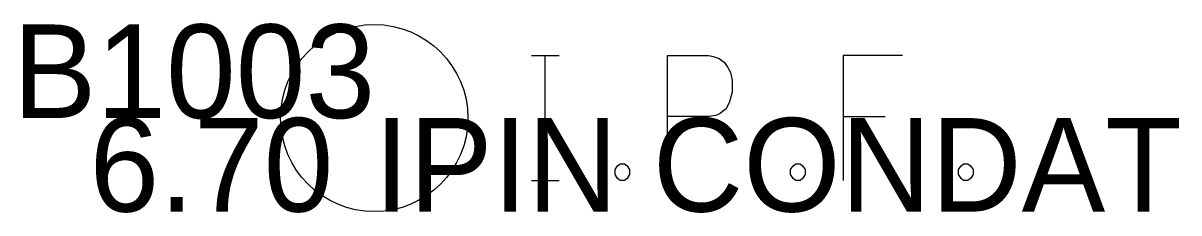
# Model space of a CAD drawing. Extents: x 2177554 to 2180444, y 721535 to 723442.
# Drawn here: x 2177888.173 to 2177888.913, y 721644.555 to 721644.677 of the extents above; entities that cross this region are included whole.
import ezdxf

# ---------------------------------------------------------------- set-up
doc = ezdxf.new("R2010")
doc.units = 0
for name, color, linetype in [('SV_X_Mon_Cells_Found', 7, 'Continuous'), ('SV_X_Text_Comment', 7, 'Continuous'), ('SV_X_Text_Elevation', 7, 'Continuous'), ('SV_X_Text_Name', 7, 'Continuous')]:
    doc.layers.add(name, color=color, linetype=linetype)

msp = doc.modelspace()

# ---------------------------------------------------------------- linework, layer by layer
at = {"layer": 'SV_X_Mon_Cells_Found'}
for points in [[(2177888.49872, 721644.656), (2177888.51636, 721644.656)], [(2177888.50754, 721644.576), (2177888.50754, 721644.656)], [(2177888.5858, 721644.576), (2177888.5858, 721644.656), (2177888.61226, 721644.656), (2177888.61502, 721644.65537), (2177888.61887, 721644.65411), (2177888.62053, 721644.65285), (2177888.62218, 721644.65159), (2177888.62438, 721644.64844), (2177888.62604, 721644.64529), (2177888.62714, 721644.64025), (2177888.62714, 721644.63269), (2177888.62659, 721644.63017), (2177888.62548, 721644.62639), (2177888.62328, 721644.62199), (2177888.62107, 721644.62009), (2177888.61942, 721644.61883), (2177888.61666, 721644.61757), (2177888.61226, 721644.61695), (2177888.5858, 721644.61695)], [(2177888.73627, 721644.656), (2177888.69823, 721644.656), (2177888.69823, 721644.576)], [(2177888.69823, 721644.61695), (2177888.72524, 721644.61695)], [(2177888.55549, 721644.58671), (2177888.55824, 721644.58671), (2177888.5599, 721644.58545), (2177888.56155, 721644.58293), (2177888.56155, 721644.57978), (2177888.5599, 721644.57726), (2177888.55824, 721644.576), (2177888.55549, 721644.576), (2177888.55383, 721644.57726), (2177888.55218, 721644.57978), (2177888.55218, 721644.58293), (2177888.55383, 721644.58545), (2177888.55549, 721644.58671)], [(2177888.66793, 721644.58671), (2177888.67068, 721644.58671), (2177888.67233, 721644.58545), (2177888.67398, 721644.58293), (2177888.67398, 721644.57978), (2177888.67233, 721644.57726), (2177888.67068, 721644.576), (2177888.66793, 721644.576), (2177888.66627, 721644.57726), (2177888.66462, 721644.57978), (2177888.66462, 721644.58293), (2177888.66627, 721644.58545), (2177888.66793, 721644.58671)], [(2177888.77539, 721644.58671), (2177888.77815, 721644.58671), (2177888.7798, 721644.58545), (2177888.78145, 721644.58293), (2177888.78145, 721644.57978), (2177888.7798, 721644.57726), (2177888.77815, 721644.576), (2177888.77539, 721644.576), (2177888.77374, 721644.57726), (2177888.77209, 721644.57978), (2177888.77209, 721644.58293), (2177888.77374, 721644.58545), (2177888.77539, 721644.58671)], [(2177888.49872, 721644.576), (2177888.51636, 721644.576)]]:
    msp.add_lwpolyline(points, dxfattribs=at)
msp.add_circle((2177888.398, 721644.616), 0.06, dxfattribs=at)

# ---------------------------------------------------------------- texts
at = {"layer": 'SV_X_Text_Comment'}
msp.add_text('IPIN CONDAT', height=0.06, dxfattribs=at).set_placement((2177888.398, 721644.556))
at = {"layer": 'SV_X_Text_Elevation'}
msp.add_text('6.70', height=0.06, dxfattribs=at).set_placement((2177888.21565, 721644.556))
at = {"layer": 'SV_X_Text_Name'}
msp.add_text('B1003', height=0.06, dxfattribs=at).set_placement((2177888.16655, 721644.616))

doc.saveas('drawing.dxf')
